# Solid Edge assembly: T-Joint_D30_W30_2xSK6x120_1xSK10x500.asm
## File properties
Author: fknapp
Template: iso metric assembly.asm
Last saved by: fknapp
Revision: 15
Application: Solid Edge
Username: fknapp
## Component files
T-Joint_D30_W30.par
SK Schraube 6x120_ohne_Gewinde.par
SK Schraube 10x500_ohne_Gewinde_22042020.par
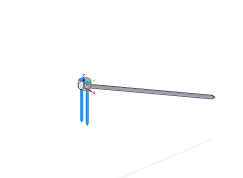
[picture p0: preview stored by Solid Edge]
